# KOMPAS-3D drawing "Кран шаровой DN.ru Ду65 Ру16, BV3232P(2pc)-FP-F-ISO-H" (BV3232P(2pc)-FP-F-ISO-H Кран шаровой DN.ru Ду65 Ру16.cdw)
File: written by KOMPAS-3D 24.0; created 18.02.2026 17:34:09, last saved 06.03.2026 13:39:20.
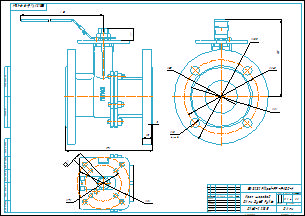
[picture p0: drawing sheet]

Document properties: Автор: R2D2; Форматы листов документа: A2; Полное имя файла: BV3232P(2pc)-FP-F-ISO-H Кран шаровой DN.ru Ду65 Ру16.m3d; Масса: 12.04; Наименование: Кран шаровой DN.ru Ду65 Ру16; Количество листов документа: 1; Примечание: D160-22135

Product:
- Component [detail]: Сборка  | qty 1  | pos. 1  | Масса: 0.046702; source file: исходные материалы\1.m3d
- Component [detail]: Сборка  | qty 1  | pos. 1  | Масса: 0.166374; Автор: R2D2; source file: исходные материалы\2.m3d
- Body: Тело 2  | qty 1
    Масса: 8.632466
- Body: Тело 3  | qty 1
    Масса: 8.632466
- Part/product: Кран шаровой DN.ru Ду65 Ру16  | designation BV3232P(2pc)-FP-F-ISO-H
    Масса: 12.04
    Раздел спецификации: Прочие изделия
    Примечание: D160-22135

Referenced files in E:\Работа\Зайцев\Для компаса\: чертеж DN.ru А3.cdt
Referenced files in E:\Работа\Зайцев\BV3232P(2pc)-FP-F-ISO-H Кран шаровой DN.ru Ду15-300 Ру16-40\DN65 PN16\: BV3232P(2pc)-FP-F-ISO-H Кран шаровой DN.ru Ду65 Ру16.m3d
Referenced files in E:\Работа\Зайцев\BV3232P(2pc)-FP-F-ISO-H Кран шаровой DN.ru Ду15-300 Ру16-40\DN65 PN16\исходные материалы\: 1.m3d, Деталь1 Деталь1.m3d, Деталь2 Деталь2.m3d, Деталь3 Деталь3.m3d, Деталь4 Деталь4.m3d, Деталь5 Деталь5.m3d, Деталь6 Деталь6.m3d, Деталь7 Деталь7.m3d, AS 1421 - M8 x 30 засверленный конец AS 1421 - M8 x 30 засверленный конец.m3d, AS 1420 - 1973 - M8 x 25 AS 1420 - 1973 - M8 x 25.m3d, ANSI B18.2.4.2M - M8x1,25 ANSI B18.2.4.2M - M8x1,25 - 13.m3d, BS 3692 - M16 BS 3692 - M16(4).m3d, 2.m3d
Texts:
  чертеж DN.ru А3.cdt
  Кран шаровой
  DN.ru Ду65 Ру16
  BV3232P(2pc)-FP-F-ISO-H
  Твердое тело1
  Деталь1
  Деталь1 Деталь1
  Деталь2
  Деталь2 Деталь2
  Деталь3
  Деталь3 Деталь3
  Деталь4
  Деталь4 Деталь4
  Деталь5
  Деталь5 Деталь5
  Деталь6
  Деталь6 Деталь6
  Деталь7
  Деталь7 Деталь7
  Solid1
  AS 1421 - M8 x 30 засверленный конец
  AS 1421 - M8 x 30 засверленный   конец
  AS 1421 - M8 x 30 засверленный   конец AS 1421 - M8 x 30 засверленный конец
  AS 1420 - 1973 - M8 x 25
  AS 1420 - 1973 - M8 x 25 AS 1420 - 1973 - M8 x 25
  ANSI B18.2.4.2M - M8x1,25 - 13
  ANSI B18.2.4.2M - M8x1,25
  ANSI B18.2.4.2M - M8x1,25 ANSI B18.2.4.2M - M8x1,25 - 13
  BS 3692 - M16(4)
  BS 3692 - M16
  BS 3692 - M16 BS 3692 - M16(4)
  Сборка
  Сборка Сборка
  Кран шаровой DN.ru Ду65 Ру16
  BV3232P(2pc)-FP-F-ISO-H Кран шаровой DN.ru Ду65 Ру16
Dimensions and other numbers on the sheet: 1:1; 0; 1; 2; 12,04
